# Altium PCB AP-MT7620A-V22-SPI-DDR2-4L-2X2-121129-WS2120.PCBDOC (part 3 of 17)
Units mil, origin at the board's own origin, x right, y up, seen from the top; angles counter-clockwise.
Board outline 7316 x 4279 mil, 4 copper layers (Top, Inner Layer 2, Inner Layer 3, Bottom), stack 35.4 mil thick; 640 components, 473 nets, 2041 pads, 2358 vias.
Unrouted connection lines stored in the file: 11.
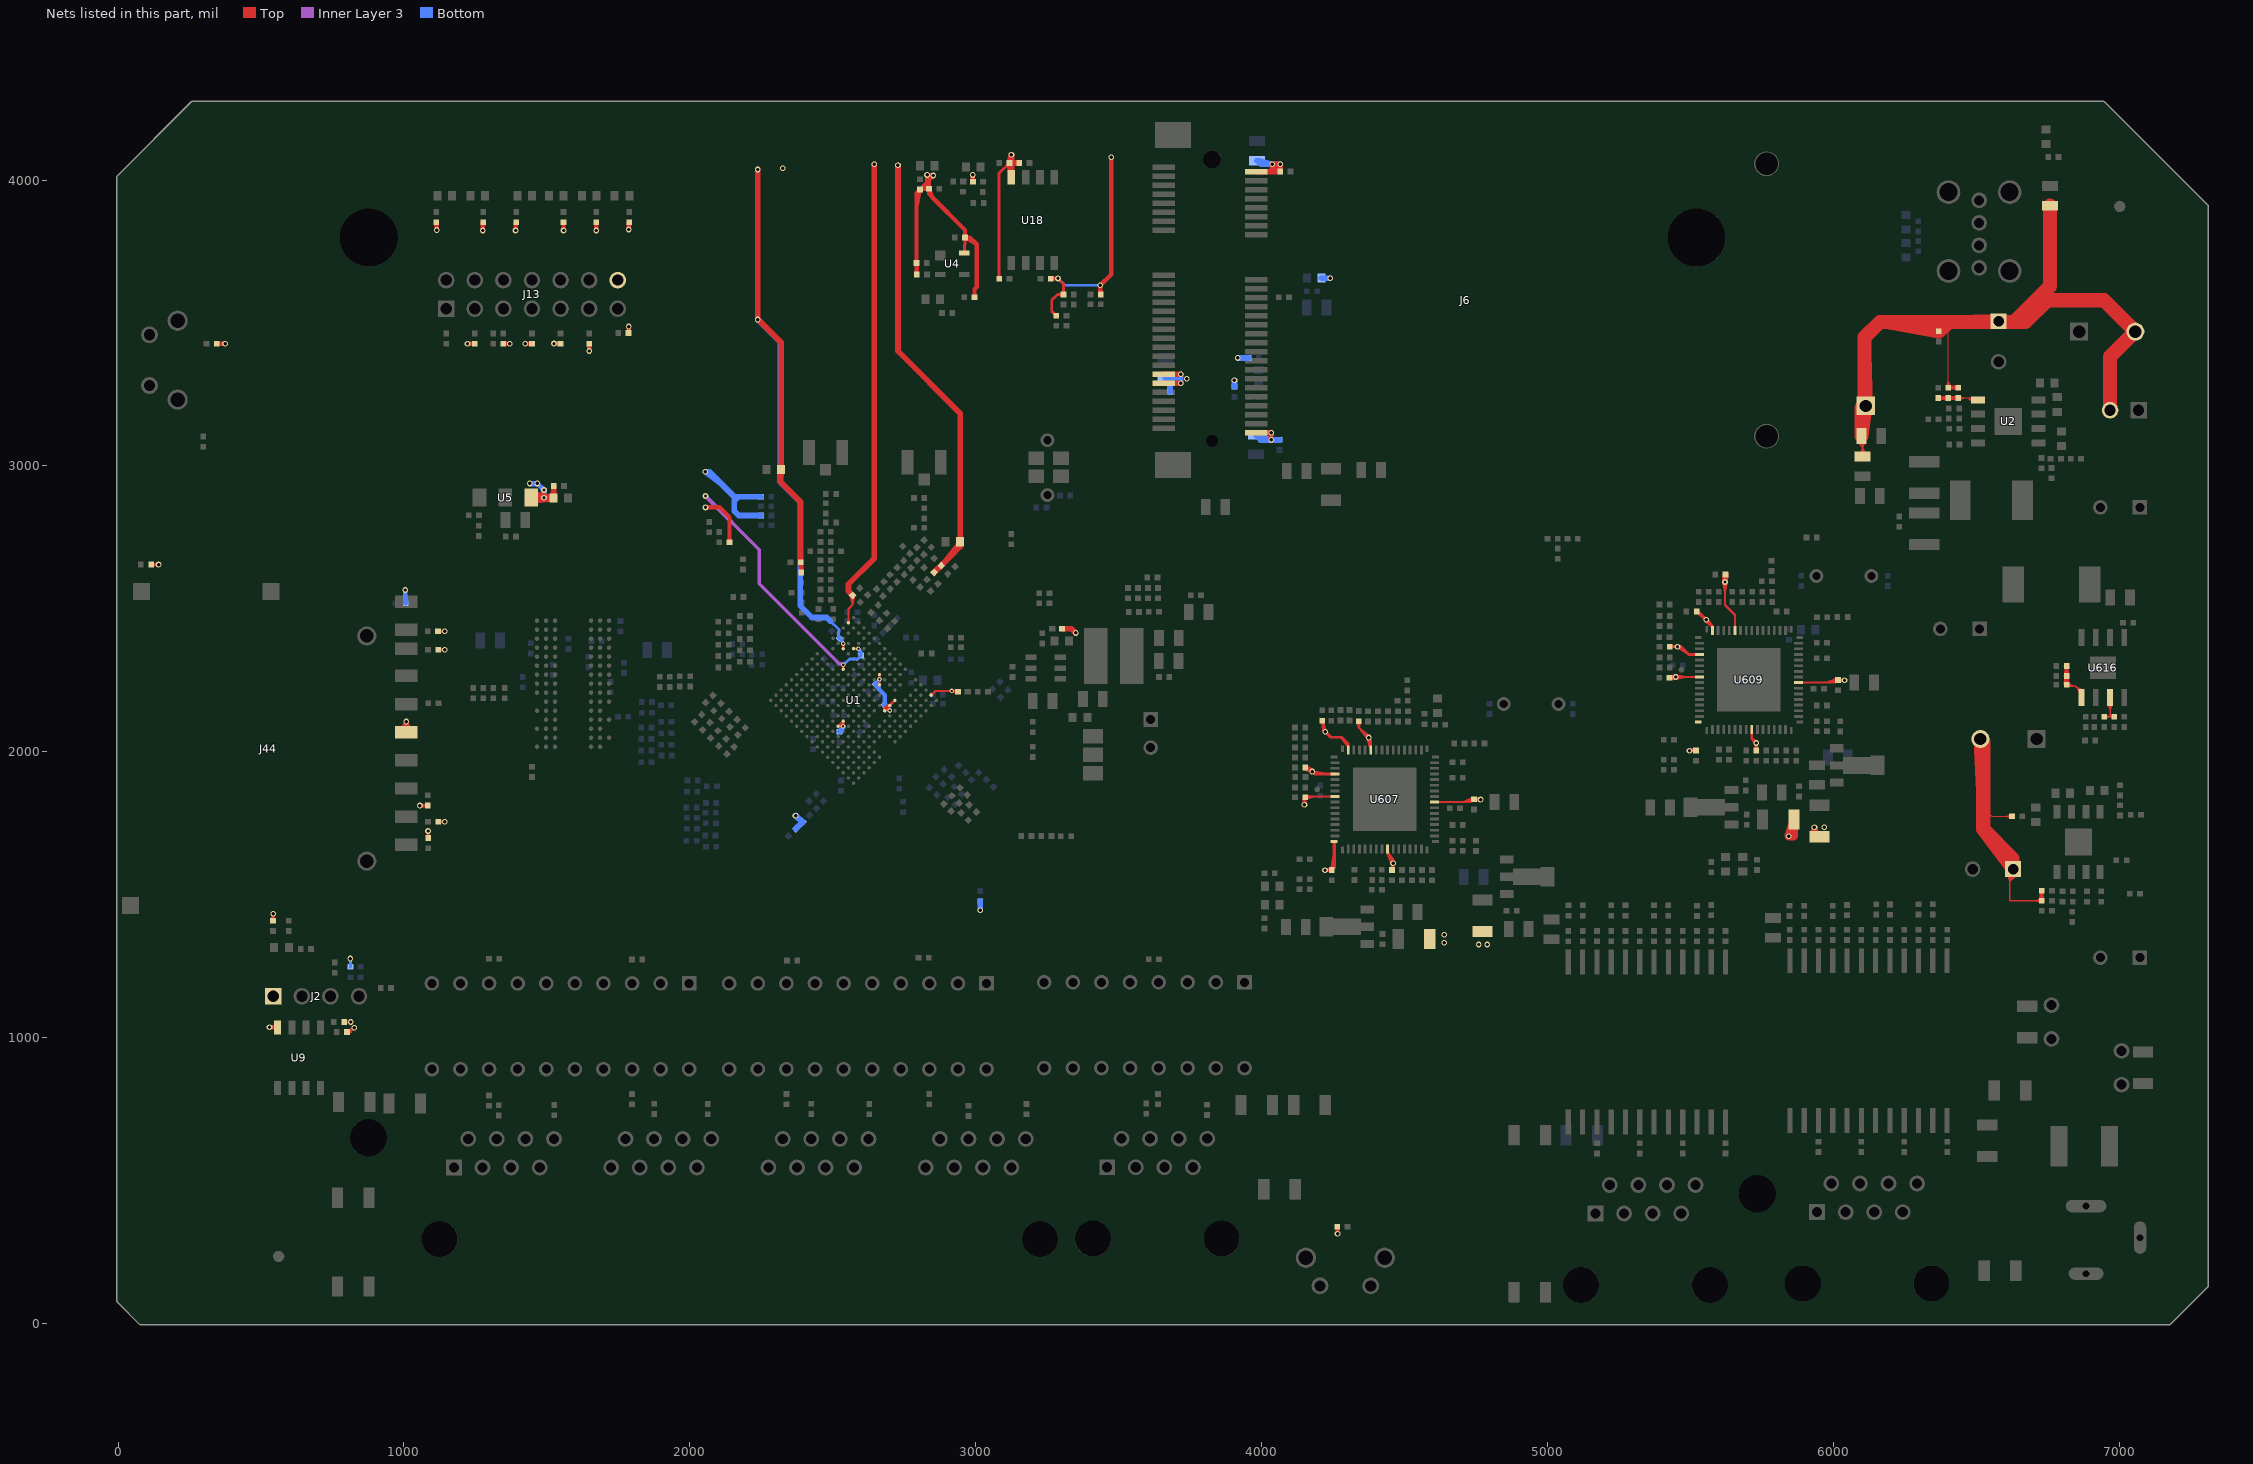
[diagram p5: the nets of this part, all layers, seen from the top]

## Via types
v1: diameter 20, hole 12, Top to Bottom, 2117 vias
v2: diameter 16, hole 8, Top to Bottom, 241 vias

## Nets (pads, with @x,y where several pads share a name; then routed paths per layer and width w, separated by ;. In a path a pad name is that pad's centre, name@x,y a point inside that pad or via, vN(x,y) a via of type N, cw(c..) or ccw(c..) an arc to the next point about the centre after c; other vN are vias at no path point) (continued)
3.3VD: C15.1 C16.1 C17.1 C39.1 C40.1 C41.1 C52.1 C53.1 C91.1 C93.1 C110.1 C137.1 C200.1 C215.1 C216.1 C222.1 C223.1 C230.1 C231.1 C232.1 C456.1 C457.1 C635.1 C636.1 C640.1 C641.1 C644.1 C645.1 C646.1 C648.1 C649.1 C652.1 C655.1 C662.1 C674.1 C684.1 C848.1 C849.1 D2.2 J2.1 J6.2 J6.39 J6.41 J6.52 J13.14 J44.4 L3.2 L5.2 L12.2 L608.1 L610.1 L613.1 L618.1 R9.1 R14.1 R27.1 R28.1 R29.1 R52.1 R53.1 R124.1 R125.1 R128.1 R129.1 R132.1 R133.1 R136.1 R137.1 R151.2 R154.1 R155.2 R156.2 R158.2 R160.2 R163.2 R165.2 R166.2 R167.2 R170.2 R221.1 R343.1 R355.1 R370.2 R371.1 R373.1 R374.2 R375.1 R376.1 R377.1 R388.1 R389.1 R416.1 R418.1 R471.1 R472.1 R473.1 R474.1 R475.1 R476.1 SR2.1 U1.A16 U1.B1 U1.D4 U1.D9 U1.E3 U1.E10 U1.E13 U1.F13 U1.G5 U1.G13 U1.M10 U1.N10 U4.4 U5.3 U9.8 U18.8 U607.9 U607.24 U607.43 U607.47 U607.52 U607.56 U607.64 U609.9 U609.24 U609.43 U609.47 U609.52 U609.56 U609.64 | length 31952
  Top w4: 6540,1786 6543,1786 6554,1775 C17.1@6625,1775 ; C17.1@6623.55,1767.13 6603,1775 ; C17.1@6623.55,1782.87 6603,1775 ; C17.1@6624.64,1771.02 6603,1775 ; C17.1@6624.64,1778.98 6603,1775
  Top w4.5: L618.1@5918.49,1707.02 v1(5934,1736) ; L618.1@5922.71,1705.13 v1(5934,1736) ; v1@5926.27,1735.4 L618.1@5932.1,1710.54 ; v1@5926.26,1736.47 L618.1@5928.58,1710.8 ; v1@5926.34,1734.82 L618.1@5934,1710.5 ; v1@5926.4,1734.48 L618.1@5935.16,1710.51 ; v1@5926.41,1737.56 L618.1@5924.97,1711.32 ; v1@5926.64,1733.59 L618.1@5938.22,1710.68 ; v1@5926.71,1738.64 L618.1@5921.21,1712.1 ; v1@5927.03,1732.62 L618.1@5941.77,1711.11 ; L618.1@5927.09,1703.86 v1(5934,1736) ; v1@5927.55,1731.71 L618.1@5945.44,1711.79 ; v1@5928.18,1730.88 L618.1@5949.32,1712.72 ; v1@5930.77,1735.65 L618.1@5935.16,1710.51 ; v1@5930.76,1735.79 L618.1@5934,1710.5 ; v1@5930.75,1736.03 L618.1@5932.1,1710.54 ; v1@5930.79,1736.48 L618.1@5928.58,1710.8 ; v1@5930.83,1735.26 L618.1@5938.22,1710.68 ; v1@5930.88,1736.93 L618.1@5924.97,1711.32 ; v1@5930.96,1734.84 L618.1@5941.77,1711.11 ; v1@5931.05,1737.36 L618.1@5921.21,1712.1 ; v1@5931.15,1734.44 L618.1@5945.44,1711.79 ; v1@5931.39,1734.06 L618.1@5949.32,1712.72 ; L618.1@5931.56,1703.22 v1(5934,1736) ; L618.1@5935.49,1703.16 v1(5934,1736) ; v1@5936.77,1734.3 L618.1@5921.21,1712.1 ; v1@5936.81,1737.63 L618.1@5949.32,1712.72 ; v1@5936.98,1734.7 L618.1@5924.97,1711.32 ; v1@5937.02,1737.21 L618.1@5945.44,1711.79 ; v1@5937.13,1735.12 L618.1@5928.58,1710.8 ; v1@5937.16,1736.77 L618.1@5941.77,1711.11 ; v1@5937.22,1735.55 L618.1@5932.1,1710.54 ; v1@5937.24,1735.79 L618.1@5934,1710.5 ; v1@5937.25,1735.94 L618.1@5935.16,1710.51 ; v1@5937.23,1736.33 L618.1@5938.22,1710.68 ; L618.1@5939.41,1703.58 v1(5934,1736) ; v1@5940.24,1731.4 L618.1@5921.21,1712.1 ; v1@5940.81,1732.29 L618.1@5924.97,1711.32 ; v1@5941,1739.32 L618.1@5949.32,1712.72 ; v1@5941.25,1733.25 L618.1@5928.58,1710.8 ; v1@5941.41,1738.26 L618.1@5945.44,1711.79 ; v1@5941.55,1734.26 L618.1@5932.1,1710.54 ; v1@5941.66,1734.82 L618.1@5934,1710.5 ; v1@5941.66,1737.19 L618.1@5941.77,1711.11 ; v1@5941.71,1735.17 L618.1@5935.16,1710.51 ; v1@5941.75,1736.11 L618.1@5938.22,1710.68 ; L618.1@5943.8,1704.62 v1(5934,1736) ; L618.1@5948.05,1706.28 v1(5934,1736) ; L618.1@5951.24,1703.16 5948.4,1706 5934,1706 v1(5934,1736) ; L618.1@5952.08,1708.54 v1(5934,1736) ; 6524,1786 6540,1786 ; C16.1@6603.62,1589.55 6617,1547.09 ; C16.1@6608.13,1590.72 6617,1547.09 ; C16.1@6612.68,1591.4 6617,1547.09 ; C16.1@6617.23,1591.61 6617,1547.09 ; C16.1@6621.74,1591.36 6617,1547.09 ; C16.1@6628.87,1590 6616.6,1590 6609,1582.4 6617,1582.4 6617,1479 C15.1@6729,1479 ; C16.1@6635.67,1587.5 6617,1547.09 ; C16.1@6639.68,1585.4 6617,1547.09 ; C16.1@6643.48,1582.88 6617,1547.09 ; C16.1@6647.03,1579.96 6617,1547.09 ; C16.1@6650.3,1576.65 6617,1547.09 ; C15.1@6721.26,1478.6 R9.1@6723.72,1505.84 ; C15.1@6721.27,1479.52 R9.1@6726.89,1505.62 ; R9.1@6721.36,1512.72 6729,1490.5 ; C15.1@6721.46,1480.81 6730.69,1502.67 ; C15.1@6721.69,1481.56 6733.37,1503.2 ; C15.1@6725.75,1478.94 R9.1@6726.89,1505.62 ; R9.1@6725.76,1513.78 6729,1490.5 ; C15.1@6725.78,1478.56 R9.1@6723.72,1505.84 ; C15.1@6725.85,1479.79 6733.37,1503.2 ; C15.1@6727.72,1471.36 6705.5,1479 ; C15.1@6727.72,1486.64 6705.5,1479 ; C15.1@6728.78,1475.76 6705.5,1479 ; C15.1@6728.78,1482.24 6705.5,1479 ; C15.1@6732.15,1479.82 R9.1@6723.72,1505.84 ; C15.1@6732.23,1478.64 6733.37,1503.2 ; C15.1@6732.25,1478.99 6730.69,1502.67 ; R9.1@6732.24,1513.78 6729,1490.5 ; C15.1@6736.32,1481.56 R9.1@6723.72,1505.84 ; C15.1@6736.56,1480.73 R9.1@6726.89,1505.62 ; R9.1@6736.64,1512.72 6729,1490.5 ; C15.1@6736.72,1479.72 6730.69,1502.67 ; C15.1@6736.75,1478.84 6733.37,1503.2 ; 6705.5,1479 C15.1@6729,1479 ; C15.1@6721.7,1481.61 6729,1490.5 ; C15.1@6721.7,1481.61 6729,1490.5 ; C15.1@6721.7,1481.61 6729,1490.5 ; C15.1@6721.7,1481.61 6729,1490.5 ; C15.1@6721.7,1481.61 6729,1490.5 ; R9.1@6723.72,1505.84 C15.1@6729,1479 ; C15.1@6725.78,1479.46 6729,1490.5 ; C15.1@6725.78,1479.46 6729,1490.5 ; C15.1@6725.78,1479.45 6730.69,1502.67 ; C15.1@6725.78,1479.46 6729,1490.5 ; C15.1@6725.78,1479.46 6729,1490.5 ; C15.1@6725.78,1479.46 6729,1490.5 ; R9.1@6726.89,1505.62 C15.1@6732.22,1479.45 ; R9.1@6726.89,1505.62 C15.1@6729,1479 ; C15.1@6729,1479 6729,1513 6730,1514 R9.1@6729,1514 6729,1490.5 ; C15.1@6729,1479 6733.37,1503.2 ; C15.1@6729,1479 6729,1490.5 ; C15.1@6729,1479 6729,1490.5 ; C15.1@6729,1479 6730.69,1502.67 ; C15.1@6729,1479 6729,1490.5 ; C15.1@6729,1479 6729,1490.5 ; 6729,1490.5 C15.1@6736.3,1481.61 ; 6729,1490.5 C15.1@6732.22,1479.46 ; 6729,1490.5 C15.1@6736.3,1481.61 ; 6729,1490.5 C15.1@6732.22,1479.46 ; 6729,1490.5 C15.1@6736.3,1481.61 ; 6729,1490.5 C15.1@6732.22,1479.46 ; 6729,1490.5 C15.1@6736.3,1481.61 ; 6729,1490.5 C15.1@6732.22,1479.46 ; 6729,1490.5 C15.1@6736.3,1481.61 ; 6729,1490.5 C15.1@6732.22,1479.46 ; 6729,1502.5 6721.36,1480.28 6729,1502.5 ; 6729,1502.5 6736.64,1480.28 6729,1502.5 ; 6729,1502.5 6725.76,1479.22 6729,1502.5 ; 6729,1502.5 6732.24,1479.22 6729,1502.5
  Top w7.5: U1.F13@2699.67,2161.9 2715,2180 2699.67,2164.67 U1.E13@2717.76,2180 U1.F13@2699.67,2161.9
  Top w8: U1.B1@2554.9,2451.43 2554.9,2500 2569.27,2514.37 ; C110.1@2563.3,2546.73 2569.27,2514.37 ; C110.1@2569.27,2547.27 2569.27,2514.37 ; C110.1@2575.25,2546.73 2569.27,2514.37 ; U1.F13@2699.67,2161.9 U1.F13@2699.67,2164.67 ; U1.E13@2715,2180 U1.E13@2717.76,2180 ; U1.A16@2844.43,2198.1 2859.33,2213 v2(2916,2213) ; R28.1@2935.32,2204.24 v2(2916,2213) ; R28.1@2937,2210 v2(2916,2213) ; R28.1@2937,2216 v2(2916,2213) ; R28.1@2938,2210 2938,2213 v2(2916,2213) ; C635.1@4153.02,1847.05 4187.44,1843.89 ; C635.1@4154,1835.14 4187.44,1843.89 ; v1@4172.08,1927.57 4164.98,1943.02 ; v1@4172.48,1927.05 C636.1@4156.57,1949.83 ; v1@4173.43,1926.17 C636.1@4153,1945 ; v1@4174.55,1925.52 C636.1@4150.55,1939.52 ; v1@4178.21,1936.88 C636.1@4150.55,1939.52 ; v1@4179.45,1936.48 C636.1@4153,1945 ; v1@4180.43,1935.92 4164.98,1943.02 ; v1@4180.57,1935.83 C636.1@4156.57,1949.83 ; 4218.01,1843.89 U607.56@4246.93,1843.89 ; U607.56@4257.76,1843.89 4155.83,1843.89 C635.1@4152.99,1841.05 4187.44,1843.89 ; C648.1@4334.06,2106.18 4340,2085 ; C648.1@4345.94,2106.18 4340,2085 ; v1@4369.18,2048.54 U607.43@4381.78,2010.73 ; v1@4369.27,2048.22 U607.43@4381.78,2018.11 ; v1@4370.46,2046.08 4346.03,2078.97 ; v1@4378.92,2054.54 4346.03,2078.97 ; v1@4380.97,2050.57 U607.43@4381.78,2010.73 ; v1@4380.96,2050.7 U607.43@4381.78,2018.11 ; U607.43@4381.78,2007.28 4381.78,2040 ; U607.9@4440.83,1660.82 4440.83,1644 ; v1@4454.4,1607.86 U607.9@4442.24,1648.07 ; v1@4454.56,1607.46 4440.83,1644 ; v1@4464.98,1613.34 4440.83,1644 ; v1@4465.24,1612.92 U607.9@4442.24,1648.07 ; U607.24@4604.22,1824.21 4729.25,1824.21 ; U607.24@4615.05,1824.21 4643.97,1824.21 ; C674.1@4741.02,1839.72 4705.45,1824.21 ; C674.1@4744.06,1828.15 4705.45,1824.21 ; v1@5445.94,2267.05 C644.1@5428.56,2253.26 ; v1@5447.35,2256.12 C644.1@5427.03,2265.05 ; v1@5447.43,2267.68 C644.1@5426.99,2259.05 ; v1@5448.11,2255.96 C644.1@5428.83,2261.89 ; v1@5448.11,2267.83 C644.1@5428.83,2261.89 ; v1@5448.96,2255.89 C644.1@5426.99,2259.05 ; v1@5449.04,2267.89 C644.1@5427.03,2265.05 ; v1@5449.5,2255.91 5485,2261.89 v1@5449.5,2267.87 ; v1@5450.57,2256.1 C644.1@5428.56,2253.26 ; 5492.01,2261.89 U609.56@5520.93,2261.89 ; U609.56@5531.76,2261.89 v1(5449,2261.89) ; v1@5550.81,2457.75 U609.47@5577.04,2436.11 ; v1@5551.2,2457.39 U609.47@5577.04,2440 ; v1@5559.65,2465.83 U609.47@5577.04,2440 ; v1@5559.92,2465.49 U609.47@5577.04,2436.11 ; U609.47@5577.04,2425.28 U609.47@5577.04,2440 ; v1@5615.02,2593.5 5621,2558 v1@5626.98,2593.5 ; v1@5615,2593.77 C652.1@5617,2619.77 ; v1@5615.04,2594.72 C652.1@5621,2619 ; v1@5615.11,2595.15 C652.1@5623,2620 ; v1@5615.53,2596.46 C652.1@5628.89,2618.85 ; v1@5626.78,2595.6 C652.1@5617,2619.77 ; v1@5626.89,2592.85 C652.1@5628.89,2618.85 ; v1@5626.96,2594.72 C652.1@5621,2619 ; v1@5627,2594.23 C652.1@5623,2620 ; U609.43@5655.78,2425.28 5655.78,2479 5621,2513.78 v1(5621,2594) ; U609.43@5655.78,2436.11 5655.78,2465.03 ; U609.9@5714.83,2067.99 5714.83,2046.17 ; U609.9@5714.83,2078.82 5714.83,2046.17 ; v1@5725.21,2027.39 5714.83,2046.17 ; v1@5733.61,2035.79 5714.83,2046.17 ; U609.24@5878.22,2242.21 6007,2242.21 6014.79,2250 6016,2250 C684.1@6016,2251 5974.78,2242.21 ; U609.24@5889.05,2242.21 5917.97,2242.21 ; C684.1@6014.33,2256.76 5974.78,2242.21 ; C684.1@6016.83,2245.06 5974.78,2242.21 ; U1.N10@2518.71,2089.52 U1.M10@2535.6,2106.4 ; U1.N10@2518.71,2089.52 2519.19,2090 U1.N10@2520,2090 ; U1.N10@2518.71,2089.52 U1.N10@2520,2090 ; U1.N10@2518.71,2089.52 U1.M10@2536.81,2107.62 ; U1.N10@2518.71,2089.52 v2(2536,2090) ; U1.N10@2518.71,2089.52 U1.M10@2535.6,2106.4 ; U1.N10@2518.71,2089.52 U1.M10@2536.81,2107.62 ; U1.N10@2518.71,2089.52 v2(2536,2090) ; U1.N10@2518.71,2089.52 v2(2536,2090) ; U1.N10@2518.71,2089.52 v2(2536,2090) ; U1.N10@2518.71,2089.52 v2(2536,2090) ; U1.N10@2518.71,2089.52 v2(2536,2090) ; U1.N10@2520,2090 U1.N10@2520,2090.81 ; U1.N10@2520,2090 v2(2536,2090) ; U1.N10@2520,2090 v2(2536,2090) ; U1.N10@2520,2090.81 U1.M10@2535.6,2106.4 ; U1.N10@2520,2090.81 U1.M10@2536.81,2107.62 ; U1.N10@2520,2090.81 v2(2536,2090) ; U1.N10@2520,2090.81 v2(2536,2090) ; U1.M10@2535.6,2106.4 U1.M10@2536.81,2107.62 ; U1.M10@2535.6,2106.4 v2(2536,2090) ; U1.M10@2535.6,2106.4 v2(2536,2090) ; U1.M10@2535.6,2106.4 v2(2536,2090) ; v2(2536,2090) v2@2536.81,2090.81 ; v2(2536,2090) U1.M10@2536.81,2107.62 ; v2(2536,2090) U1.M10@2536.81,2107.62 ; v2(2536,2090) U1.M10@2536.81,2107.62 ; v2(2536,2090) U1.M10@2536.81,2107.62 ; v2(2536,2090) U1.M10@2536.81,2107.62 ; v2@2536.81,2090.81 U1.M10@2536.81,2107.62 ; v2@2536.81,2090.81 U1.M10@2536.81,2107.62 ; U1.D4@2573,2360.95 v2(2590,2361) U1.D4@2573,2360.95 ; U1.D4@2573,2360.95 v2(2590,2361) U1.D4@2573,2360.95 ; U1.E10@2663.48,2234.29 2664.12,2233.64 U1.E10@2663.48,2234.29 ; U1.E10@2663.48,2234.29 v2(2663.5,2254) ; U1.E10@2663.48,2234.29 v2(2663.5,2254) ; U1.E10@2663.48,2234.29 v2(2663.5,2254) ; U1.E10@2663.48,2234.29 v2(2663.5,2254) ; v2(2663.5,2254) U1.D9@2663.48,2270.48 ; v2(2663.5,2254) U1.D9@2663.48,2270.48 ; v2(2663.5,2254) U1.D9@2663.48,2270.48 ; C636.1@4150.55,1939.52 v1(4177,1931) ; C636.1@4153,1945 4152,1945 4153.98,1943.02 4164.98,1943.02 ; C636.1@4153,1945 4164.98,1943.02 ; C636.1@4153,1945 v1(4177,1931) ; C636.1@4153,1945 4164.98,1943.02 ; C636.1@4156.57,1949.83 v1(4177,1931) ; 4164.98,1943.02 v1(4177,1931) ; 4164.98,1943.02 4155.41,1950.49 4164.98,1943.02 ; 4164.98,1943.02 4153.51,1939.02 4164.98,1943.02 ; 4340,2085 v1(4375,2050) ; 4340,2085 C648.1@4340,2107 4340,2085 ; 4346.03,2078.97 v1(4375,2050) ; v1(4375,2050) 4375,2046.78 4381.78,2040 ; v1(4375,2050) U607.43@4381.78,2010.73 ; v1(4375,2050) U607.43@4381.78,2018.11 ; U607.43@4381.78,2018.11 4381.78,2040 ; 4440.83,1644 4460,1623.84 ; 4440.83,1644 U607.9@4440.83,1649.99 ; 4440.83,1644 U607.9@4440.83,1649.99 ; 4440.83,1644 v1(4460,1610) ; U607.9@4440.83,1649.99 4460,1623.84 ; U607.9@4442.24,1648.07 v1(4460,1610) ; v1@4454.14,1611.3 4460,1623.84 ; v1@4454.14,1611.3 4460,1623.84 ; v1@4454.14,1611.3 4460,1623.84 ; v1(4460,1610) 4460,1623.84 ; v1(4460,1610) 4460,1623.84 ; v1(4460,1610) 4460,1623.84 ; 4460,1623.84 v1@4465.86,1611.3 ; 4460,1623.84 v1@4465.86,1611.3 ; 4460,1623.84 v1@4465.86,1611.3 ; 4705.45,1824.21 C674.1@4742.99,1834.05 ; 4729.25,1824.21 4741.04,1836 C674.1@4742.99,1834.05 ; 4729.25,1824.21 4745.56,1828.63 4729.25,1824.21 ; 4729.25,1824.21 4738.69,1838.23 4729.25,1824.21 ; 4729.25,1824.21 C674.1@4742.99,1834.05 ; 4729.25,1824.21 C674.1@4742.99,1834.05 ; C644.1@5426.99,2259.05 5425.99,2259.05 C644.1@5428.83,2261.89 ; C644.1@5426.99,2259.05 v1(5449,2261.89) ; C644.1@5427.03,2265.05 v1(5449,2261.89) ; C644.1@5427.03,2265.05 v1(5449,2261.89) ; C644.1@5428.56,2253.26 v1(5449,2261.89) ; C644.1@5428.83,2261.89 v1(5449,2261.89) ; U609.47@5577.04,2436.11 v1(5555.02,2462.02) U609.47@5577.04,2440 ; C652.1@5617,2619.77 v1(5621,2594) ; v1(5621,2594) C652.1@5621,2619 ; v1(5621,2594) C652.1@5628.89,2618.85 ; v1(5621,2594) C652.1@5623,2620 ; C652.1@5621,2619 5622,2620 C652.1@5623,2620 ; 5714.83,2046.17 v1(5730,2031) 5714.83,2046.17 ; U1.E3@2536.81,2360.95 v2(2536.8,2378.8) U1.E3@2536.81,2360.95 ; U1.G13@2681.57,2143.81 2681.57,2150.57 2683.29,2152.29 U1.G13@2681.57,2143.81
  Top w10: v2(2590,2361) v2(2590,2361) ; U4.4@2960.32,3744.8 2960.32,3770.09 2963,3772.76 C200.1@2963,3799 ; R170.2@3082,3655 3082,4024 C137.1@3118,4060 3086.79,4028.79 ; v1(3288,3656) 3307,3637 R133.1@3307,3600 ; 4212.01,1922.63 U607.52@4246.93,1922.63 ; 4223.36,1922.63 v1(4177,1931) 4185.37,1922.63 U607.52@4257.76,1922.63 ; U607.47@4303.04,2007.28 4303.04,2026.96 ; 5494.11,2340.89 v1(5455,2368) ; U609.52@5520.93,2340.63 5494.37,2340.63 ; U609.52@5531.76,2340.63 5494.37,2340.63 ; R52.1@801,1020 812.6,1020 ; R52.1@801,1020 v1(826.04,1034.88) ; R52.1@801,1020 812.6,1021.44 ; R52.1@801,1020 812.6,1021.44 ; R52.1@801,1020 812.6,1020 ; R52.1@801,1020 v1(826.04,1034.88) ; 812.6,1020 812.6,1021.44 ; 812.6,1021.44 v1(826.04,1034.88) ; 812.6,1021.44 v1(826.04,1034.88) ; U1.G5@2536.81,2288.57 U1.G5@2537,2288.76 ; U1.G5@2536.81,2288.57 v2(2537,2305) ; U1.G5@2536.81,2288.57 v2(2537,2305) ; U1.G5@2537,2288.76 v2(2537,2305) ; U1.G5@2537,2288.76 v2(2537,2305) ; 3266,3541 3266,3580.28 3285.72,3600 ; 3266,3541 R124.1@3282,3525 3266,3541 ; 3285.72,3600 R133.1@3307,3600 ; 3285.72,3600 R133.1@3307,3600 ; C641.1@4212,2109 4212,2110 C641.1@4216,2106 ; C641.1@4212,2109 v1@4216,2077 ; C641.1@4212,2109 v1(4223,2070) ; v1@4216,2077 C641.1@4216,2106 ; v1@4216,2077 v1(4223,2070) ; C641.1@4216,2106 v1(4223,2070) ; v1(4223,2070) 4242,2051 4279,2051 ; 4279,2051 4303.04,2026.96 ; 4279,2051 U607.47@4303.04,2018.11 ; U607.47@4303.04,2018.11 4303.04,2026.96 ; U607.47@4303.04,2018.11 4303.04,2026.96 ; C655.1@4455.99,1587.05 4455.99,1586.05 C655.1@4460,1586.05 ; C655.1@4455.99,1587.05 v1(4460,1610) ; C655.1@4455.99,1587.05 v1(4460,1610) ; C655.1@4460,1586.05 v1(4460,1610) ; C655.1@4460,1586.05 v1(4460,1610) ; C645.1@5427.04,2368 5426.99,2368.05 C645.1@5427.99,2368.05 ; C645.1@5427.04,2368 v1(5455,2368) ; C645.1@5427.04,2368 v1(5455,2368) ; C645.1@5427.99,2368.05 v1(5455,2368) ; C645.1@5427.99,2368.05 v1(5455,2368) ; v1(5455,2368) 5467,2368 5494.37,2340.63 ; C684.1@6016,2250 C684.1@6016,2251 ; C684.1@6016,2250 v1(6039,2250) ; C684.1@6016,2250 v1(6039,2250) ; C684.1@6016,2251 v1(6039,2250) ; C684.1@6016,2251 v1(6039,2250) ; R53.1@791,1055 v1(814,1055) R53.1@791,1055
  Top w12: R389.1@116,2655 v1(142,2655) ; 4253.82,1638.26 C640.1@4245.99,1587.05 4253.82,1594.88 U607.64@4253.82,1686.41 4253.82,1645.49 ; R371.1@1084.5,1699.5 v1(1084.5,1723) ; R371.1@1084.5,1699.5 R371.1@1085,1699 v1(1084.5,1723) ; R371.1@1084.5,1699.5 v1(1084.5,1723) ; 2686.75,2155.75 2692.9,2161.9 U1.F13@2699.67,2161.9 2686.75,2155.75 ; 2686.75,2155.75 2688.25,2155.75 ; 2686.75,2155.75 2683.29,2152.29 U1.G13@2681.57,2143.81 2686.75,2155.75 ; 2688.25,2155.75 v2(2699.5,2144.5) 2688.25,2155.75 ; v1(5497,2004) v1@5498.05,2005.05 ; v1(5497,2004) C646.1@5519.99,2005.05 ; v1(5497,2004) C646.1@5519.99,2005.05 ; v1@5498.05,2005.05 C646.1@5519.99,2005.05 ; v1@5498.05,2005.05 C646.1@5519.99,2005.05 ; C649.1@5522,2491 C649.1@5526.04,2491 ; C649.1@5522,2491 v1(5555.02,2462.02) ; C649.1@5522,2491 v1(5555.02,2462.02) ; C649.1@5526.04,2491 v1(5555.02,2462.02) ; C649.1@5526.04,2491 v1(5555.02,2462.02) ; C662.1@5730,2005.06 v1(5730,2031) ; C662.1@5729.99,2005.05 v1(5730,2031) ; C662.1@5730,2005.06 v1(5730,2031) ; C662.1@5729.99,2005.05 v1(5730,2031) ; R158.2@542,1409 542,1433 v1(543,1434) R158.2@542,1409 ; v1(1056,1812) R377.1@1083,1812 v1(1056,1812) ; R375.1@1119,2422 v1(1143,2422) R375.1@1119,2422 ; R373.1@1120,1755 v1(1143,1755) R373.1@1120,1755 ; R376.1@1120,2357 v1(1143,2357) R376.1@1120,2357 ; v1(4150,1815) 4150,1838.06 C635.1@4152.99,1841.05 v1(4150,1815)
  Top w15: R154.1@345.44,3427.2 v1(374.48,3427.2) ; J44.4@1021.9,2071.39 v1(1008,2106) ; v1(1648,3402) R472.1@1648,3427 ; R132.1@2139,2733 2139,2821 2104,2856 ; 2793,3906.74 R374.2@2805,3967 ; R343.1@2996,3590 2996,3617.84 3004,3625.84 3004,3775.5 ; v1(3474,4080) 3474,3670 v1(3436,3632) ; v1(1008,2106) J44.4@1008,2068.7 v1(1008,2106) ; v1(1008,2106) 994.1,2071.39 v1(1008,2106) ; R160.2@1113,3852 1115,3850 v1(1115,3825) ; R160.2@1113,3852 v1(1115,3825) ; R160.2@1113,3852 v1(1115,3825) ; R475.1@1348,3427 R475.1@1348.2,3427.2 ; R475.1@1348,3427 v1(1370.36,3427.2) ; R475.1@1348,3427 v1(1370.36,3427.2) ; R475.1@1348.2,3427.2 v1(1370.36,3427.2) ; R475.1@1348.2,3427.2 v1(1370.36,3427.2) ; R167.2@1558,3852 1558.52,3851.48 v1(1558.52,3823.68) ; R167.2@1558,3852 v1(1558.52,3823.68) ; R167.2@1558,3852 v1(1558.52,3823.68) ; 2104,2856 2056,2856 v1(2055,2855) 2104,2856 ; D2.2@2793,3710 2793,3955 ; D2.2@2793,3710 2794,3709 R14.1@2794,3670 D2.2@2793,3710 ; 2793,3955 R374.2@2805,3967 ; 2793,3955 R374.2@2805,3967 ; 2793,3955 R374.2@2805,3967 ; R374.2@2805,3967 2808,3970 R136.1@2837,3970 ; R374.2@2805,3967 R374.2@2806.68,3967 ; R374.2@2805,3967 R136.1@2837,3970 ; R374.2@2805,3967 2830,3990.32 ; R374.2@2805,3967 R136.1@2837,3970 ; R374.2@2806.68,3967 2830,3990.32 ; R374.2@2806.68,3967 R136.1@2837,3970 ; 2830,3990.32 v1@2830,4017 ; 2830,3990.32 R136.1@2837,3970 ; 2830,3990.32 R136.1@2837,3970 ; 2830,3990.32 v1(2830,4018) ; v1@2830,4017 v1(2830,4018) ; v1@2830,4017 v1@2852,4017 ; v1@2830,4017 v1(2852,4016) ; v1(2830,4018) v1@2852,4017 ; v1(2830,4018) v1(2852,4016) ; v1(2830,4018) 2837,4001 ; v1(2830,4018) v1(2852,4016) ; v1(2830,4018) v1(2852,4016) ; v1(2830,4018) 2837,4001 ; 2837,3952.5 R136.1@2837,3970 ; 2837,3952.5 2848,3941.5 ; 2837,3952.5 R136.1@2837,3970 ; 2837,3952.5 R136.1@2837,3970 ; R136.1@2837,3970 2837,4001 ; R136.1@2837,3970 2848,3941.5 ; 2837,4001 v1(2852,4016) ; 2837,4001 v1(2852,4016) ; 2848,3941.5 2848,3940 2963,3825 C200.1@2963,3799 ; v1(2852,4016) v1@2852,4017 ; C200.1@2963,3799 2980.5,3799 ; C200.1@2963,3799 3004,3775.5 ; C200.1@2963,3799 2980.5,3799 ; 2980.5,3799 3004,3775.5 ; R370.2@2990,3994 v1(2990,4018) ; R370.2@2990,3994 R370.2@2991,3994 v1(2990,4018) ; R370.2@2990,3994 v1(2990,4018) ; R125.1@3436,3600 v1(3436,3632) ; R125.1@3436,3600 R125.1@3438,3600 v1(3436,3632) ; R125.1@3436,3600 v1(3436,3632) ; v1(4222,1586) v1@4223.05,1587.05 ; v1(4222,1586) C640.1@4245.99,1587.05 ; v1(4222,1586) C640.1@4245.99,1587.05 ; v1@4223.05,1587.05 C640.1@4245.99,1587.05 ; v1@4223.05,1587.05 C640.1@4245.99,1587.05 ; R355.1@4265,338.5 4266,337.5 v1(4266,314) ; R355.1@4265,338.5 v1(4266,314) ; R355.1@4265,338.5 v1(4266,314) ; v1(530,1037) 556.51,1037 U9.8@558,1035.51 v1(530,1037) ; v1(1222.52,3427.2) 1247.8,3427.2 R476.1@1248,3427 v1(1222.52,3427.2) ; v1(1276.28,3823.68) 1276.28,3850.28 R166.2@1278,3852 v1(1276.28,3823.68) ; v1(1390.52,3823.68) 1390.52,3849.52 R165.2@1393,3852 v1(1390.52,3823.68) ; v1(1424.12,3427.2) 1447.8,3427.2 R474.1@1448,3427 v1(1424.12,3427.2) ; v1(1525,3428) 1547,3428 R473.1@1548,3427 v1(1525,3428) ; v1(1672.76,3823.68) 1672.76,3851.76 R163.2@1673,3852 v1(1672.76,3823.68) ; R471.1@1786,3465 1786,3486.68 v1(1787,3487.68) R471.1@1786,3465 ; v1(1787,3827) 1787,3851 R155.2@1788,3852 v1(1787,3827) ; C848.1@2388,2663 2390,2661 L12.2@2390,2627 C848.1@2388,2663 ; SR2.1@3263,3655 3263,3656 v1(3288,3656) SR2.1@3263,3655 ; C674.1@4742.99,1834.05 4764.95,1834.05 v1(4766,1833) C674.1@4742.99,1834.05
  Top w20: 2238,3584 v1(2238,3512) ; 2238,3965 v1(2238,4037) v1@2238,3514 ; 2293.31,3458.69 v1(2238,3512) ; C457.1@2319.59,2986 2317,2945 ; C457.1@2319.59,2990 2319.59,3064 ; C848.1@2388,2663 2388,2874 2317,2945 ; 2645,3983 v1(2645,4055) 2645,2676.5 2555.13,2586.63 2555.13,2561.41 ; 2728,3980 v1(2728,4052) 2728,3402 2945.59,3184.41 C456.1@2945.59,2735 2945.59,2718.59 ; 2895.27,2668.27 C456.1@2945.59,2733 ; 2928.53,2701.53 C849.1@2879.73,2651.27 ; C456.1@2945.59,2737 2945.59,2811 ; R27.1@3302,2431 3335,2431 ; R27.1@3303,2431 3335,2431 ; J6.39@3658,3320.59 J6.39@3658.41,3321 ; J6.52@3980.83,3115.87 J6.52@3980.97,3116 ; J6.2@3980.83,4029.25 4038.4,4029.25 ; J6.2@4010.36,4029.25 4038.4,4029.25 ; v1(1490,2889) C53.1@1522.39,2889.02 ; v1(1490,2889) U5.3@1445.55,2889.02 C53.1@1522.39,2889.02 ; v1(1490,2889) C53.1@1522.39,2889.02 ; v1(1490,2889) 1446.76,2875.45 C53.1@1522.39,2889.02 ; v1(1490,2889) C53.1@1523.41,2888 ; v1(1490,2889) 1449.38,2889.02 C53.1@1523.41,2888 ; v1(1490,2889) 1523.41,2886 1450.15,2876.06 v1(1490,2889) ; v1(1490,2889) C53.1@1522.39,2889.02 ; v1(1490,2889) 1446.76,2902.58 C53.1@1522.39,2889.02 ; v1(1490,2889) C53.1@1523.41,2890 ; v1(1490,2889) 1450.45,2901.92 C53.1@1523.41,2890 ; C53.1@1522.39,2889.02 C53.1@1523.41,2888 ; C53.1@1523.41,2888 1524,2888.59 C52.1@1524,2930 C53.1@1523.41,2890 ; v1(2238,3512) v1@2238,3514 ; v1@2238,3514 2319.59,3432.41 C457.1@2319.59,2988 2317,2985.41 2317,2945 ; 2555.13,2561.41 C110.1@2569.27,2547.27 2555.13,2561.41 ; 2868.5,2641.5 2945.59,2718.59 ; 2868.5,2641.5 L5.2@2854.73,2627.73 C849.1@2879.73,2651.27 ; 2868.5,2641.5 2878.27,2651.27 C849.1@2879.73,2651.27 ; 2868.5,2641.5 C849.1@2879.73,2651.27 ; 2868.5,2641.5 C849.1@2879.73,2651.27 ; 2868.5,2641.5 C849.1@2879.73,2651.27 ; 2945.59,2718.59 C456.1@2945.59,2733 ; 2945.59,2718.59 C456.1@2945.59,2733 ; C137.1@3118,4060 C137.1@3125,4060 ; C137.1@3118,4060 v1(3125,4089) C137.1@3125,4058 ; C137.1@3118,4060 R151.2@3152,4060 ; C137.1@3118,4060 R151.2@3152,4060 ; C137.1@3118,4060 U18.8@3125,4009.8 C137.1@3125,4058 ; C137.1@3118,4060 3125,4021.02 C137.1@3125,4058 ; C137.1@3124,4060 C137.1@3125,4060 ; C137.1@3124,4060 R151.2@3152,4060 ; C137.1@3124,4060 R151.2@3152,4060 ; C137.1@3125,4058 C137.1@3125,4060 ; 3335,2431 v1(3350,2416) 3335,2431 ; J6.39@3658.41,3321 v1(3717,3321) ; J6.39@3658.41,3321 v1(3717,3321) ; v1(3717,3289) v1@3717,3289.09 ; v1(3717,3289) 3687.53,3289.09 v1@3717,3289.09 ; v1(3717,3289) J6.41@3658,3289.09 v1@3717,3289.09 ; v1(3717,3321) 3687.53,3320.59 v1(3717,3321) ; J6.52@3980.97,3116 v1(4034,3116) ; J6.52@3980.97,3116 v1(4034,3116) ; v1(4034,3116) v1(4034,3091) v1(4034,3116) ; v1(4034,3116) 4010.36,3115.87 v1(4034,3116) ; v1(4037,4055.4) 4038.4,4054 4038.4,4043 ; v1(4037,4055.4) 4038.4,4043 ; v1(4037,4055.4) 4038.4,4043 ; v1(4037,4055.4) 4038.4,4029.25 ; v1(4037,4055.4) 4065,4043 ; v1(4037,4055.4) 4038.4,4043 ; v1(4037,4055.4) C216.1@4065,4030 ; v1(4037,4055.4) 4038.4,4043 ; v1(4037,4055.4) v1(4065,4055) ; v1(4037,4055.4) v1(4065,4055) ; 4038.4,4029.25 4064.25,4029.25 C216.1@4065,4030 ; 4038.4,4029.25 4038.4,4043 ; 4038.4,4029.25 C216.1@4065,4030 ; 4038.4,4043 4065,4043 ; 4038.4,4043 C216.1@4065,4030 ; 4038.4,4043 v1(4065,4055) ; C216.1@4065,4030 4065,4043 ; C216.1@4065,4030 4065,4043 ; C216.1@4065,4030 v1(4065,4055) ; C216.1@4065,4030 v1(4065,4055) ; C216.1@4065,4030 v1(4065,4055) ; 4065,4043 v1(4065,4055)
  Top w30: v1(5844,1705) 5862.11,1705 ; v1(5844,1705) L610.1@5862.11,1763.05 5862.11,1705 ; v1(5844,1705) 5862.11,1705 ; v1(5844,1705) 5862.11,1747.3 5862.11,1705 ; v1(5844,1705) 5862.11,1705
  Top w50: 6524,1862 L3.2@6514.57,2045 6524,2035.57 6524,1786 6524,1730 ; 6524,1730 6626.9,1627.1 ; 6524,1730 C16.1@6628.87,1590 ; 6626.9,1627.1 6626.9,1590 C16.1@6628.87,1590 ; 6626.9,1627.1 C16.1@6628.87,1590 ; 6626.9,1627.1 C16.1@6628.87,1590
  Inner Layer 3 w12: v1(2055,2895) 2243,2707 2243,2588.13 2522.53,2308.6 ; 2522.53,2308.6 2537,2308.6 v2(2537,2305) 2522.53,2308.6
  Bottom w4: v1(1440,2939) v1(1466,2939) ; v1@1440.33,2935.01 v1@1464,2939 ; v1@1440.33,2942.99 v1@1464,2939 ; v1@1441.33,2931.11 v1@1464,2939 ; v1@1441.33,2946.89 v1@1464,2939 ; v1@1461.35,2932.49 v1@1486.74,2919.26 ; v1@1462.37,2931.87 v1@1442.55,2946.46 ; v1@1462.37,2946.13 v1@1442.55,2931.54 ; v1@1463.45,2935.92 v1@1486.74,2919.26 ; v1@1463.49,2931.4 v1@1442.14,2942.68 ; v1@1463.49,2946.6 v1@1442.14,2935.32 ; v1@1464.48,2935.3 v1@1442.55,2946.46 ; v1@1464.48,2942.7 v1@1442.55,2931.54 ; v1@1464.67,2931.11 v1@1442,2939 ; v1@1464.67,2946.89 v1@1442,2939 ; v1@1465.06,2935.11 v1@1442.14,2942.68 ; v1@1465.06,2942.89 v1@1442.14,2935.32 ; v1@1465.67,2935.01 v1@1442,2939 ; v1@1465.67,2942.99 v1@1442,2939 ; v1@1465.89,2931 v1@1442.14,2935.32 ; v1@1465.89,2947 v1@1442.14,2942.68 ; v1@1466.28,2935.01 v1@1442.14,2935.32 ; v1@1466.28,2942.99 v1@1442.14,2942.68 ; v1@1466.9,2935.1 v1@1442.55,2931.54 ; v1@1466.9,2942.9 v1@1442.55,2946.46 ; v1@1467.16,2931.08 v1@1442.55,2931.54 ; v1@1467.16,2946.92 v1@1442.55,2946.46 ; v1@1468.95,2941.7 v1@1486.74,2919.26 ; v1@1472.27,2943.97 v1@1486.74,2919.26 ; v1@1482,2889.16 v1@1486.48,2912.88 ; v1@1482.07,2887.95 v1@1482.86,2912.52 ; v1@1482.11,2890.33 v1@1490,2913 ; v1@1482.11,2914.67 v1@1490,2892 ; v1@1482.39,2891.46 v1@1493.52,2912.88 ; v1@1482.7,2912.73 v1@1475.74,2938.04 ; v1@1482.83,2892.54 v1@1497.14,2912.52 ; v1@1483.15,2911.86 v1@1472.49,2937.23 ; v1@1483.62,2911.18 v1@1469.51,2936.49 ; v1@1483.71,2911.06 v1@1469.35,2935.81 ; v1@1484.28,2910.41 v1@1468.47,2932.32 ; v1@1484.91,2909.82 v1@1467.7,2929.18 ; v1@1486.01,2888.75 v1@1486.48,2912.88 ; v1@1486.01,2889.33 v1@1490,2913 ; v1@1486.01,2915.67 v1@1490,2892 ; v1@1486.09,2888.15 v1@1482.86,2912.52 ; v1@1486.1,2889.91 v1@1493.52,2912.88 ; v1@1486.28,2890.47 v1@1497.14,2912.52 ; v1@1486.49,2914.09 v1@1475.74,2938.04 ; v1@1486.74,2913.69 v1@1472.49,2937.23 ; v1@1486.98,2913.37 v1@1469.51,2936.49 ; v1@1487.04,2913.31 v1@1469.35,2935.81 ; v1@1487.35,2913 v1@1468.47,2932.32 ; v1@1487.7,2912.72 v1@1467.7,2929.18 ; v1@1491.76,2919.59 v1@1467.7,2929.18 ; v1@1492.17,2919.36 v1@1468.47,2932.32 ; v1@1492.56,2919.07 v1@1469.35,2935.81 ; v1@1492.63,2919.02 v1@1469.51,2936.49 ; v1@1492.89,2918.76 v1@1472.49,2937.23 ; v1@1492.96,2923.43 v1@1467.7,2929.18 ; v1@1493.18,2918.42 v1@1475.74,2938.04 ; v1@1493.72,2890.47 v1@1482.86,2912.52 ; v1@1493.84,2923.02 v1@1468.47,2932.32 ; v1@1493.91,2888.15 v1@1497.14,2912.52 ; v1@1493.9,2889.91 v1@1486.48,2912.88 ; v1@1493.99,2888.75 v1@1493.52,2912.88 ; v1@1493.99,2889.33 v1@1490,2913 ; v1@1493.99,2915.67 v1@1490,2892 ; v1@1494.68,2922.49 v1@1469.35,2935.81 ; v1@1494.82,2922.38 v1@1469.51,2936.49 ; v1@1495.37,2921.93 v1@1472.49,2937.23 ; v1@1495.98,2921.32 v1@1475.74,2938.04 ; v1@1497.17,2892.54 v1@1482.86,2912.52 ; v1@1497.61,2891.46 v1@1486.48,2912.88 ; v1@1497.89,2890.33 v1@1490,2913 ; v1@1497.89,2914.67 v1@1490,2892 ; v1@1497.93,2887.95 v1@1497.14,2912.52 ; v1@1498,2889.16 v1@1493.52,2912.88 ; v1@4064.08,4055.4 4064.48,4055 v1(4065,4055) ; v1@1442,2939 v1(1466,2939) ; v1@1442.14,2935.32 v1(1466,2939) ; v1@1442.14,2942.68 v1(1466,2939) ; v1@1442.55,2931.54 v1(1466,2939) ; v1@1442.55,2946.46 v1(1466,2939) ; v1(1466,2939) 1467,2939 v1(1490,2916) ; v1(1466,2939) v1@1486.74,2919.26 ; v1@1467.7,2929.18 v1(1490,2916) ; v1@1468.47,2932.32 v1(1490,2916) ; v1@1469.35,2935.81 v1(1490,2916) ; v1@1469.51,2936.49 v1(1490,2916) ; v1@1472.49,2937.23 v1(1490,2916) ; v1@1475.74,2938.04 v1(1490,2916) ; v1@1482.86,2912.52 v1(1490,2889) ; v1@1486.48,2912.88 v1(1490,2889) ; v1(1490,2889) v1(1490,2916) ; v1(1490,2889) v1@1497.14,2912.52 ; v1(1490,2889) v1@1493.52,2912.88
  Bottom w10: 2491.4,2458 2521.41,2427.99 2521.41,2419.91 2520.81,2419.3 2520.81,2417.61 2520,2416.8 ; v1(3288,3656) 3312,3632 v1(3436,3632) 3394,3632 ; 2520,2416.8 2520,2397.27 2521.36,2398.64 C93.1@2522.73,2397.27 ; 2520,2416.8 C93.1@2522.73,2397.27 ; C93.1@2522.73,2397.27 2535,2385 2535,2380.6 v2(2536.8,2378.8) C93.1@2522.73,2397.27 ; 2558.12,2324.5 2537.81,2304.19 v2(2537,2305) 2558.12,2324.5 ; 2558.12,2324.5 2582.54,2324.5 2583.78,2323.26 ; 2583.78,2323.26 2586.36,2323.26 ; 2583.78,2323.26 C91.1@2599.9,2336.8 ; 2586.36,2323.26 C91.1@2599.9,2336.8 ; 2586.36,2323.26 C91.1@2599.9,2336.8 ; 2586.36,2323.26 C91.1@2599.9,2336.8 ; C91.1@2599.9,2336.8 2599.9,2351.1 ; C91.1@2599.9,2336.8 2599.9,2351.1 ; C91.1@2599.9,2336.8 v2(2590,2361) 2599.9,2351.1 ; v1(812.6,1276.8) 813,1276.4 R137.1@813,1248 v1(812.6,1276.8)
  Bottom w12: C40.1@2649.15,2236.41 2663.5,2250.76 v2(2663.5,2254) C40.1@2649.15,2236.41
  Bottom w15: C41.1@2522.72,2071.28 v2@2538.72,2087.28 ; C41.1@2522.72,2071.28 2524,2071.28 C41.1@2524,2070 ; C41.1@2522.72,2071.28 v2(2536,2090) ; C41.1@2524,2070 v2@2538.72,2087.28 ; C41.1@2524,2070 v2(2536,2090) ; v2(2536,2090) v2@2538.72,2087.28 ; 2661.4,2219.01 2682,2198.41 ; 2661.4,2219.01 2661.4,2223.92 C40.1@2649.15,2236.41 2661.4,2219.01 ; C39.1@2680.23,2163.77 v2(2699.5,2144.5) ; C39.1@2680.23,2163.77 C39.1@2680.73,2164.27 ; C39.1@2680.23,2163.77 v2(2699.5,2144.5) ; C39.1@2680.73,2164.27 2681.36,2163.64 2682,2164.27 2682,2198.41 ; C39.1@2680.73,2164.27 2682,2198.41 ; C39.1@2680.73,2164.27 v2(2699.5,2144.5) ; C39.1@2680.73,2164.27 v2(2699.5,2144.5) ; R388.1@1005,2520 R388.1@1006,2520 v1(1005,2566) R388.1@1005,2520
  Bottom w20: 2115.62,2932.38 v1(2054,2980) ; 2179,2892.51 R129.1@2249,2892.5 2167.57,2892.51 ; 2180,2826.5 R128.1@2250,2826.5 2170.99,2826.5 2155.49,2842 2155.49,2878 ; v1(2238,3512) 2316,3434 2316,2944 2386,2874 2386,2511.64 2427.64,2470 2479.4,2470 2491.4,2458 ; R29.1@2394.27,1753.27 C215.1@2370.73,1730.73 2393.98,1753.98 R29.1@2394.98,1753.98 ; C232.1@3664,3308.55 C232.1@3681,3308.55 ; C230.1@3980,3109.45 3995,3094.45 3995,3091 v1(4034,3091) ; C231.1@3984,4067.55 3985.85,4067.55 3998,4055.4 v1(4037,4055.4) ; C231.1@3995,4067.55 v1(4037,4055.4) ; v1@4064.08,4055.4 v1(4037,4055.4) ; v1(4065,4055) v1(4037,4055.4) ; v1(2054,2980) 2068,2980 ; v1(2054,2980) 2068,2980 ; 2068,2980 2155.49,2892.51 ; 2155.49,2878 2155.49,2892.51 ; 2155.49,2878 2167.57,2890.08 2167.57,2892.51 ; 2155.49,2892.51 2167.57,2892.51 ; v1(2370,1776) v1@2371.34,1777.34 ; v1(2370,1776) R29.1@2394.84,1753.84 ; v1(2370,1776) R29.1@2394.98,1753.98 ; v1@2371.34,1777.34 R29.1@2394.84,1753.84 ; v1@2371.34,1777.34 R29.1@2394.98,1753.98 ; R29.1@2394.84,1753.84 R29.1@2394.98,1753.98 ; C232.1@3675,3308.55 3703,3308.55 ; C232.1@3675,3308.55 C222.1@3681,3260 C232.1@3681,3308.55 ; C232.1@3675,3308.55 v1(3717,3321) ; C232.1@3681,3308.55 3703,3308.55 ; C232.1@3681,3308.55 v1(3717,3321) ; 3703,3308.55 3704.55,3308.55 ; 3703,3308.55 v1@3717,3294.55 ; 3703,3308.55 v1(3717,3289) ; 3703,3308.55 v1(3717,3321) ; 3703,3308.55 v1(3717,3321) ; 3703,3308.55 v1(3717,3321) ; 3703,3308.55 v1(3717,3321) ; 3703,3308.55 v1(3717,3321) ; 3704.55,3308.55 v1(3717,3321) ; 3704.55,3308.55 v1(3717,3321) ; 3704.55,3308.55 v1(3717,3321) ; v1(3717,3289) v1@3717,3294.55 ; v1(3717,3289) v1(3717,3321) ; v1@3717,3294.55 v1(3717,3321) ; v1(4034,3091) 4062,3091 C223.1@4063,3092 v1(4034,3091) ; v1(4034,3091) 3991,3109.45 v1(4034,3091) ; R418.1@4209.39,3657.2 R418.1@4209.59,3657 ; R418.1@4209.39,3657.2 v1(4240,3657) ; R418.1@4209.39,3657.2 v1(4240,3657) ; R418.1@4209.59,3657 v1(4240,3657) ; R418.1@4209.59,3657 v1(4240,3657) ; v1(3016,1446) R221.1@3016,1477 v1(3016,1446) ; R416.1@3905,3277 v1(3905,3300) R416.1@3905,3277 ; v1(3917,3378) R156.2@3954,3378 v1(3917,3378)
  other v1: 4760,1326 4789,1326 4639,1332 4639,1360 5968,1735.9 3738,3305 2325,4041
5EN_5-POWER0: C317.1 R268.2 U616.7 | length 398.1
  Top w4.5: C317.1@6948.1,2119.75 6968,2122 ; C317.1@6948.43,2126.22 6968,2122 ; C317.1@6949.12,2115.33 6968,2122 ; C317.1@6949.88,2130.52 6968,2122 ; U616.7@6960.32,2169.89 6968,2147.64 ; U616.7@6964.72,2170.95 6968,2147.64 ; U616.7@6968,2171.18 6968,2147.64 ; U616.7@6968,2190.67 6968,2122 ; U616.7@6971.28,2170.95 6968,2147.64 ; U616.7@6975.68,2169.89 6968,2147.64 ; R268.2@6980.51,2130.34 6968,2122 ; R268.2@6981.5,2115.4 6968,2122 ; R268.2@6982.43,2126.2 6968,2122 ; R268.2@6982.86,2119.75 6968,2122 ; 6968,2122 6983,2122 R268.2@6983,2123 6968,2122 ; 6968,2122 6949,2122 C317.1@6948,2123 6968,2122
5V: C4.1 C5.1 C6.1 C219.1 J12.1 J14.2 L2.2 R3.1 R356.1 R417.2 | length 5824
  Top w4: R3.1@6394.13,3275.45 6402,3296 ; R3.1@6398.02,3274.36 6402,3296 ; R3.1@6402,3274 6402,3501.9 6404,3503.9 ; R3.1@6405.98,3274.36 6402,3296 ; R3.1@6409.87,3275.45 6402,3296
  Top w4.5: C219.1@6084.8,3088.67 6102.5,3063.4 ; R417.2@6088.19,3036.52 6102.5,3063.45 ; C219.1@6088.74,3091.02 6102.5,3063.4 ; R417.2@6092.4,3034.67 6102.5,3063.45 ; C219.1@6092.94,3092.74 6102.5,3063.4 ; R417.2@6096.78,3033.49 6102.5,3063.45 ; C219.1@6098.55,3094 6102.5,3063.4 ; C219.1@6098.55,3105 6102.5,3105 R417.2@6102.5,3032.95 ; C219.1@6104.3,3094.2 6102.5,3063.4 ; R417.2@6108.22,3033.49 6102.5,3063.45 ; C219.1@6108.79,3093.6 6102.5,3063.4 ; R417.2@6112.6,3034.67 6102.5,3063.45 ; C219.1@6113.21,3092.34 6102.5,3063.4 ; R417.2@6116.81,3036.52 6102.5,3063.45 ; C6.1@6361.36,3472.28 6369,3494.5 ; C6.1@6365.76,3471.22 6369,3494.5 ; C6.1@6369,3471 6369,3503.9 ; C6.1@6372.24,3471.22 6369,3494.5 ; C6.1@6376.64,3472.28 6369,3494.5 ; R3.1@6402.22,3270.76 6425.5,3274 ; R3.1@6402.22,3277.24 6425.5,3274 ; R3.1@6403.28,3266.36 6425.5,3274 ; R3.1@6403.28,3281.64 6425.5,3274 ; C4.1@6434.44,3266.69 6413.1,3278.27 ; C4.1@6434.44,3281.31 6412.8,3269.63 ; C4.1@6435.19,3266.46 6413.41,3275.68 ; C4.1@6435.19,3281.54 6413.33,3272.31 ; C4.1@6436.22,3270.85 6413.1,3278.27 ; C4.1@6436.21,3277.15 6412.8,3269.63 ; C4.1@6436.28,3266.28 6413.33,3272.31 ; C4.1@6436.28,3281.72 6413.41,3275.68 ; C4.1@6437.01,3270.75 6413.33,3272.31 ; C4.1@6437.01,3277.25 6413.41,3275.68 ; C4.1@6437.16,3266.25 6412.8,3269.63 ; C4.1@6437.13,3281.75 6413.1,3278.27 ; C4.1@6437.36,3270.77 6412.8,3269.63 ; C4.1@6437.36,3277.23 6413.1,3278.27 ; 6412.8,3269.63 C4.1@6437,3274 ; 6413.1,3278.27 C4.1@6437,3274 ; 6413.33,3272.31 C4.1@6436.55,3277.22 ; 6413.33,3272.31 C4.1@6437,3274 ; 6413.41,3275.68 C4.1@6436.55,3270.78 ; 6413.41,3275.68 C4.1@6437,3274 ; 6413.5,3274 6435.72,3266.36 6413.5,3274 ; 6413.5,3274 6435.72,3281.64 6413.5,3274 ; 6413.5,3274 6436.78,3270.76 6413.5,3274 ; 6413.5,3274 6436.78,3277.24 6413.5,3274 ; 6425.5,3274 R3.1@6402,3274 6400,3275 6402,3273 6403,3274 C4.1@6437,3274 ; 6425.5,3274 C4.1@6434.39,3266.7 ; 6425.5,3274 C4.1@6434.39,3281.3 ; 6425.5,3274 C4.1@6436.54,3270.78 ; 6425.5,3274 C4.1@6436.54,3277.22 ; 6425.5,3274 C4.1@6437,3274 ; 6425.5,3274 C4.1@6434.39,3266.7 ; 6425.5,3274 C4.1@6434.39,3281.3 ; 6425.5,3274 C4.1@6436.54,3270.78 ; 6425.5,3274 C4.1@6436.54,3277.22 ; 6425.5,3274 C4.1@6437,3274 ; 6425.5,3274 C4.1@6434.39,3266.7 ; 6425.5,3274 C4.1@6434.39,3281.3 ; 6425.5,3274 C4.1@6436.54,3270.78 ; 6425.5,3274 C4.1@6436.54,3277.22 ; 6425.5,3274 C4.1@6437,3274 ; 6425.5,3274 C4.1@6434.39,3266.7 ; 6425.5,3274 C4.1@6434.39,3281.3 ; 6425.5,3274 C4.1@6436.54,3270.78 ; 6425.5,3274 C4.1@6436.54,3277.22 ; 6425.5,3274 C4.1@6437,3274 ; 6425.5,3274 C4.1@6434.39,3266.7 ; 6425.5,3274 C4.1@6434.39,3281.3 ; 6425.5,3274 C4.1@6436.54,3270.78 ; 6425.5,3274 C4.1@6436.54,3277.22
  Top w50: 6109.1,3392.7 J12.1@6113,3210 ; 6186.14,3503.9 C6.1@6369,3471 ; C5.1@6578,3503.9 6404,3503.9 ; R356.1@6758,3910.55 6758,3628.9 6633,3503.9 ; J14.2@6968,3195 6968,3381.57 ; J12.1@6098.55,3203.35 C219.1@6098.55,3105 J12.1@6113,3210 ; J12.1@6098.55,3203.35 J12.1@6109.1,3213.9 ; J12.1@6098.55,3203.35 6098.55,3116 J12.1@6113,3210 ; J12.1@6109.1,3213.9 6109.1,3450 6163,3503.9 6369,3503.9 ; J12.1@6109.1,3213.9 J12.1@6113,3210 ; C6.1@6369,3471 6404,3503.9 ; C6.1@6369,3471 6369,3503.9 ; C6.1@6369,3471 6369,3503.9 ; 6369,3503.9 6404,3503.9 ; 6404,3503.9 6633,3503.9 ; 6404,3503.9 C5.1@6578,3505.87 ; 6404,3503.9 C5.1@6578,3505.87 ; C5.1@6578,3505.87 6633,3503.9 ; 6633,3503.9 6671.9,3503.9 6748,3580 6946.43,3580 ; 6946.43,3580 L2.2@7056.43,3470 ; 6946.43,3580 L2.2@7056.43,3470 ; 6968,3381.57 L2.2@7056.43,3470 ; 6968,3381.57 L2.2@7056.43,3470
5V_FB_1_5-POWER0: C308.2 R270.2 R271.1 U616.5 | length 2386.7
  Top w4.5: C308.2@6808.27,2235.5 R270.2@6813.63,2258.5 ; R270.2@6808.25,2264.74 6811.32,2288.87 ; R270.2@6808.27,2265.57 6813.85,2288.45 ; C308.2@6808.28,2234.36 R270.2@6810.18,2258.42 ; R270.2@6808.3,2265.86 R271.1@6816,2300 ; R270.2@6808.31,2265.95 6815,2288.53 ; R271.1@6808.31,2299.05 6815,2276.47 ; R270.2@6808.36,2263.72 C308.2@6816,2241.5 ; R270.2@6808.43,2266.65 6817.4,2289.62 ; C308.2@6808.52,2237.03 R270.2@6818.37,2258.5 ; R270.2@6808.65,2267.46 R271.1@6820.3,2290.02 ; C308.2@6808.88,2238.05 R270.2@6821.82,2258.42 ; C308.2@6812.75,2234.9 R270.2@6813.63,2258.5 ; R270.2@6812.76,2264.78 C308.2@6816,2241.5 ; R270.2@6812.75,2264.93 6813.85,2288.45 ; R270.2@6812.75,2265.09 6815,2288.53 ; R270.2@6812.75,2265.15 R271.1@6816,2300 ; R270.2@6812.77,2265.4 6817.4,2289.62 ; R271.1@6812.75,2299.91 6815,2276.47 ; C308.2@6812.8,2234.43 R270.2@6810.18,2258.42 ; C308.2@6812.8,2235.55 R270.2@6818.37,2258.5 ; R270.2@6812.78,2264.59 6811.32,2288.87 ; R270.2@6812.84,2265.75 R271.1@6820.3,2290.02 ; C308.2@6812.91,2235.99 R270.2@6821.82,2258.42 ; C308.2@6815.55,2231.78 6840.07,2230 ; C308.2@6815.64,2227.26 6840.07,2230 ; C308.2@6816.87,2238.13 6840.07,2230 ; C308.2@6818.75,2242.25 6840.07,2230 ; C308.2@6819.09,2235.99 R270.2@6810.18,2258.42 ; R270.2@6819.14,2265.84 6811.32,2288.87 ; C308.2@6819.2,2234.43 R270.2@6821.82,2258.42 ; C308.2@6819.2,2235.55 R270.2@6813.63,2258.5 ; R270.2@6819.21,2265.52 6813.85,2288.45 ; C308.2@6819.25,2234.9 R270.2@6818.37,2258.5 ; R270.2@6819.23,2264.66 R271.1@6820.3,2290.02 ; R270.2@6819.24,2264.78 C308.2@6816,2241.5 ; R270.2@6819.25,2265.03 6817.4,2289.62 ; R270.2@6819.25,2265.15 R271.1@6816,2300 ; R270.2@6819.23,2265.36 6815,2288.53 ; R271.1@6819.23,2299.64 6815,2276.47 ; C308.2@6823.12,2238.05 R270.2@6810.18,2258.42 ; R270.2@6823.27,2267.68 6811.32,2288.87 ; C308.2@6823.48,2237.03 R270.2@6813.63,2258.5 ; R270.2@6823.5,2266.97 6813.85,2288.45 ; R270.2@6823.58,2266.6 6815,2288.53 ; R271.1@6823.58,2298.4 6815,2276.47 ; R270.2@6823.64,2263.72 C308.2@6816,2241.5 ; C308.2@6823.72,2234.36 R270.2@6821.82,2258.42 ; R270.2@6823.71,2265.78 6817.4,2289.62 ; R270.2@6823.7,2265.86 R271.1@6816,2300 ; C308.2@6823.73,2235.5 R270.2@6818.37,2258.5 ; R270.2@6823.75,2264.87 R271.1@6820.3,2290.02 ; U616.5@6861.67,2205.61 6851.35,2226.65 ; U616.5@6865.53,2207.99 6851.35,2226.65 ; U616.5@6868,2190.67 6868,2210 6848,2230 6816,2230 C308.2@6816,2235 ; U616.5@6868,2210.16 6851.35,2226.65 ; U616.5@6870.15,2212.65 6851.35,2226.65 ; U616.5@6872.49,2216.53 6851.35,2226.65 ; R270.2@6808.5,2266.96 6815,2276.47 ; R270.2@6808.5,2266.96 6815,2276.47 ; R270.2@6808.5,2266.96 6815,2276.47 ; R270.2@6808.5,2266.96 6815,2276.47 ; R270.2@6808.5,2266.96 6815,2276.47 ; R270.2@6810.18,2258.42 C308.2@6816,2235 ; 6811.32,2288.87 R270.2@6816,2265 ; R270.2@6812.75,2265.18 6815,2276.47 ; R270.2@6812.75,2265.18 6815,2276.47 ; R270.2@6812.75,2265.18 6815,2276.47 ; R270.2@6812.75,2265.18 6815,2276.47 ; R270.2@6812.75,2265.18 6815,2276.47 ; R270.2@6813.63,2258.5 C308.2@6816,2235 ; 6813.85,2288.45 R270.2@6816,2265 ; R270.2@6815,2265 6816,2264 C308.2@6816,2235 ; R270.2@6815,2265 R270.2@6816,2265 ; R270.2@6815,2265 6815,2300 R271.1@6816,2300 ; 6815,2276.47 R271.1@6816,2300 ; 6815,2276.47 R270.2@6823.04,2268.23 ; 6815,2276.47 R270.2@6819.17,2265.74 ; 6815,2276.47 R270.2@6816,2265 ; 6815,2276.47 R270.2@6823.04,2268.23 ; 6815,2276.47 R270.2@6819.17,2265.74 ; 6815,2276.47 R270.2@6816,2265 ; 6815,2276.47 R270.2@6823.04,2268.23 ; 6815,2276.47 R270.2@6819.17,2265.74 ; 6815,2276.47 R270.2@6816,2265 ; 6815,2276.47 R270.2@6823.04,2268.23 ; 6815,2276.47 R270.2@6819.17,2265.74 ; 6815,2276.47 R270.2@6816,2265 ; 6815,2276.47 R270.2@6823.04,2268.23 ; 6815,2276.47 R270.2@6819.17,2265.74 ; 6815,2276.47 R270.2@6816,2265 ; 6815,2288.53 R270.2@6816,2265 ; C308.2@6816,2235 6840.07,2230 ; C308.2@6816,2235 R270.2@6821.82,2258.42 ; C308.2@6816,2235 R270.2@6818.37,2258.5 ; C308.2@6816,2235 R270.2@6816,2258.5 ; C308.2@6816,2241.5 R270.2@6816,2265 ; R270.2@6816,2258.5 6808.36,2236.28 R270.2@6816,2258.5 ; R270.2@6816,2258.5 6823.64,2236.28 R270.2@6816,2258.5 ; R270.2@6816,2258.5 6812.76,2235.22 R270.2@6816,2258.5 ; R270.2@6816,2258.5 6819.24,2235.22 R270.2@6816,2258.5 ; R270.2@6816,2265 R271.1@6820.3,2290.02 ; R270.2@6816,2265 6817.4,2289.62 ; R270.2@6816,2265 R271.1@6816,2300
5V_FB_5-POWER0: C4.2 R3.2 R5.1 U2.5 | length 2787.7
  Top w4: C4.2@6437,3238 6500.67,3238 6507.67,3231 U2.5@6506.39,3231 ; C4.2@6437.36,3234.02 6459,3238 ; C4.2@6437.36,3241.98 6459,3238 ; C4.2@6438.45,3230.13 6459,3238 ; C4.2@6438.45,3245.87 6459,3238 ; U2.5@6489.61,3221.93 6469.53,3238 ; U2.5@6491.89,3225.28 6469.53,3238 ; U2.5@6493.59,3228.91 6469.53,3238 ; U2.5@6494.28,3231 6469.53,3238 ; U2.5@6494.79,3233.15 6469.53,3238 ; U2.5@6495.06,3241.18 6469.53,3238 ; U2.5@6495.24,3237.13 6469.53,3238
  Top w4.5: R5.1@6367.09,3241.25 6390.53,3239 ; R5.1@6367.36,3234.77 6390.53,3239 ; R5.1@6367.95,3245.69 6390.53,3239 ; R5.1@6368.6,3230.42 6390.53,3239 ; R3.2@6399.31,3230.73 6378.48,3242.57 ; R3.2@6399.54,3245.35 R5.1@6376.98,3233.7 ; R3.2@6400.03,3230.5 6378.55,3240.15 ; R3.2@6400.35,3245.57 6377.38,3236.6 ; R3.2@6400.4,3230.42 6378.47,3239 ; R3.2@6401.05,3245.69 6378.47,3239 ; R3.2@6401.14,3230.3 R5.1@6367,3238 ; R3.2@6401.17,3234.86 6378.48,3242.57 ; R3.2@6401.14,3245.7 R5.1@6367,3238 ; R3.2@6401.22,3230.29 6377.38,3236.6 ; R3.2@6401.25,3241.16 R5.1@6376.98,3233.7 ; R3.2@6401.43,3245.73 6378.55,3240.15 ; R3.2@6401.48,3234.79 6378.55,3240.15 ; R3.2@6401.6,3241.23 6377.38,3236.6 ; R3.2@6401.64,3234.77 6378.47,3239 ; R3.2@6401.85,3234.75 R5.1@6367,3238 ; R3.2@6401.85,3241.25 R5.1@6367,3238 ; R3.2@6401.91,3241.25 6378.47,3239 ; R3.2@6401.97,3234.75 6377.38,3236.6 ; R3.2@6402.07,3241.25 6378.55,3240.15 ; R3.2@6402.09,3241.25 6425.52,3239 ; R3.2@6402.13,3230.25 R5.1@6376.98,3233.7 ; R3.2@6402.23,3245.75 6378.48,3242.57 ; R3.2@6402.4,3241.23 6378.48,3242.57 ; R3.2@6402.95,3245.69 6425.52,3239 ; R3.2@6403.6,3230.42 6425.52,3239 ; C4.2@6434.31,3230.73 6413.48,3242.57 ; C4.2@6434.54,3245.35 R3.2@6411.98,3233.7 ; C4.2@6435.03,3230.5 6413.55,3240.15 ; C4.2@6435.35,3245.57 6412.38,3236.6 ; C4.2@6435.4,3230.42 6413.47,3239 ; C4.2@6436.05,3245.69 6413.47,3239 ; C4.2@6436.14,3230.3 R3.2@6402,3238 ; C4.2@6436.17,3234.86 6413.48,3242.57 ; C4.2@6436.14,3245.7 R3.2@6402,3238 ; C4.2@6436.22,3230.29 6412.38,3236.6 ; C4.2@6436.25,3241.16 R3.2@6411.98,3233.7 ; C4.2@6436.43,3245.73 6413.55,3240.15 ; C4.2@6436.48,3234.79 6413.55,3240.15 ; C4.2@6436.6,3241.23 6412.38,3236.6 ; C4.2@6436.64,3234.77 6413.47,3239 ; C4.2@6436.85,3234.75 R3.2@6402,3238 ; C4.2@6436.85,3241.25 R3.2@6402,3238 ; C4.2@6436.91,3241.25 6413.47,3239 ; C4.2@6436.97,3234.75 6412.38,3236.6 ; C4.2@6437.07,3241.25 6413.55,3240.15 ; C4.2@6437.13,3230.25 R3.2@6411.98,3233.7 ; C4.2@6437.23,3245.75 6413.48,3242.57 ; C4.2@6437.34,3234.77 R3.2@6411.98,3233.7 ; C4.2@6437.4,3241.23 6413.48,3242.57 ; R5.1@6367,3238 6367,3239 R3.2@6402,3239 ; R5.1@6367,3238 6390.53,3239 ; R5.1@6367,3238 R3.2@6402,3238 ; R5.1@6376.98,3233.7 6402.34,3234.77 6425.52,3239 ; R5.1@6376.98,3233.7 R3.2@6402,3238 ; 6377.38,3236.6 R3.2@6402,3238 ; 6378.47,3239 R3.2@6402,3238 ; 6378.48,3242.57 R3.2@6402,3238 ; 6378.55,3240.15 R3.2@6402,3238 ; 6390.53,3239 R3.2@6398.77,3230.96 ; 6390.53,3239 R3.2@6400.04,3245.5 ; 6390.53,3239 R3.2@6401.26,3234.83 ; 6390.53,3239 R3.2@6401.82,3241.25 ; 6390.53,3239 R3.2@6402,3238 ; 6390.53,3239 R3.2@6398.77,3230.96 ; 6390.53,3239 R3.2@6400.04,3245.5 ; 6390.53,3239 R3.2@6401.26,3234.83 ; 6390.53,3239 R3.2@6401.82,3241.25 ; 6390.53,3239 R3.2@6402,3238 ; 6390.53,3239 R3.2@6398.77,3230.96 ; 6390.53,3239 R3.2@6400.04,3245.5 ; 6390.53,3239 R3.2@6401.26,3234.83 ; 6390.53,3239 R3.2@6401.82,3241.25 ; 6390.53,3239 R3.2@6402,3238 ; 6390.53,3239 R3.2@6398.77,3230.96 ; 6390.53,3239 R3.2@6400.04,3245.5 ; 6390.53,3239 R3.2@6401.26,3234.83 ; 6390.53,3239 R3.2@6401.82,3241.25 ; 6390.53,3239 R3.2@6402,3238 ; 6390.53,3239 R3.2@6398.77,3230.96 ; 6390.53,3239 R3.2@6400.04,3245.5 ; 6390.53,3239 R3.2@6401.26,3234.83 ; 6390.53,3239 R3.2@6401.82,3241.25 ; 6390.53,3239 R3.2@6402,3238 ; R3.2@6402,3238 R3.2@6402,3239 ; R3.2@6402,3238 6425.52,3239 ; R3.2@6402,3238 C4.2@6437,3238 ; R3.2@6402,3239 6436,3239 C4.2@6437,3238 ; R3.2@6411.98,3233.7 C4.2@6437,3238 ; 6412.38,3236.6 C4.2@6437,3238 ; 6413.47,3239 C4.2@6437,3238 ; 6413.48,3242.57 C4.2@6437,3238 ; 6413.55,3240.15 C4.2@6437,3238 ; 6425.52,3239 C4.2@6433.77,3230.96 ; 6425.52,3239 C4.2@6435.04,3245.5 ; 6425.52,3239 C4.2@6436.26,3234.83 ; 6425.52,3239 C4.2@6436.82,3241.25 ; 6425.52,3239 C4.2@6437,3238 ; 6425.52,3239 C4.2@6433.77,3230.96 ; 6425.52,3239 C4.2@6435.04,3245.5 ; 6425.52,3239 C4.2@6436.26,3234.83 ; 6425.52,3239 C4.2@6436.82,3241.25 ; 6425.52,3239 C4.2@6437,3238 ; 6425.52,3239 C4.2@6433.77,3230.96 ; 6425.52,3239 C4.2@6435.04,3245.5 ; 6425.52,3239 C4.2@6436.26,3234.83 ; 6425.52,3239 C4.2@6436.82,3241.25 ; 6425.52,3239 C4.2@6437,3238 ; 6425.52,3239 C4.2@6433.77,3230.96 ; 6425.52,3239 C4.2@6435.04,3245.5 ; 6425.52,3239 C4.2@6436.26,3234.83 ; 6425.52,3239 C4.2@6436.82,3241.25 ; 6425.52,3239 C4.2@6437,3238 ; 6425.52,3239 C4.2@6433.77,3230.96 ; 6425.52,3239 C4.2@6435.04,3245.5 ; 6425.52,3239 C4.2@6436.26,3234.83 ; 6425.52,3239 C4.2@6436.82,3241.25 ; 6425.52,3239 C4.2@6437,3238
